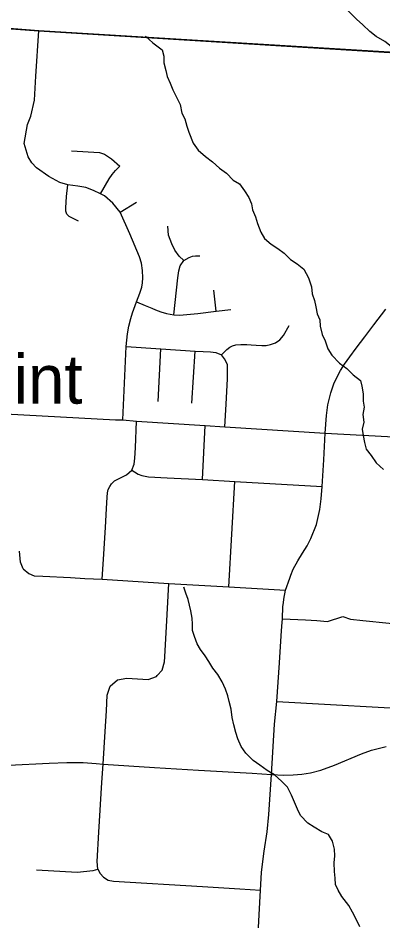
# Model space of a CAD drawing. Extents: x 0 to 34, y 0 to 22.
# Drawn here: x 4.859 to 5.448, y 5.875 to 7.332 of the extents above; entities that cross this region are included whole.
import ezdxf

# ---------------------------------------------------------------- set-up
doc = ezdxf.new("R2010")
doc.units = 0
for name, color, linetype in [('GM_X_City_Street', 7, 'Continuous'), ('GM_X_Corporation', 7, 'Continuous'), ('GM_X_County_Road', 7, 'Continuous'), ('GM_X_Minor_River', 7, 'Continuous'), ('GM_X_Township_Road', 7, 'Continuous'), ('GM_X_Unincorporated_Text', 7, 'Continuous')]:
    doc.layers.add(name, color=color, linetype=linetype)

msp = doc.modelspace()

# ---------------------------------------------------------------- linework, layer by layer
at = {"layer": 'GM_X_City_Street'}
for p, q in [((5.0238, 7.0188), (5.0499, 7.035)), ((5.1788, 6.8591), (5.1747, 6.893)), ((5.0849, 6.7133), (5.0895, 6.7981)), ((5.1392, 6.7103), (5.1448, 6.7947)), ((5.1928, 6.6725), (5.1949, 6.7087)), ((5.1566, 6.5872), (5.161, 6.6742)), ((5.1989, 6.4142), (5.2088, 6.584)), ((5.1989, 6.4142), (5.2908, 6.4087))]:
    msp.add_line(p, q, dxfattribs=at)
for points in [[(5.0282, 6.6834), (5.0336, 6.8021), (5.0356, 6.8225), (5.0377, 6.835), (5.0407, 6.847), (5.0438, 6.8564), (5.0502, 6.8742), (5.0553, 6.8879), (5.0585, 6.8979), (5.0596, 6.9048), (5.0601, 6.9129), (5.0599, 6.9249), (5.0583, 6.9364), (5.055, 6.9469), (5.0392, 6.984), (5.0238, 7.0188), (5.0118, 7.0332), (4.9983, 7.0451), (4.9922, 7.0487), (4.9809, 7.0541), (4.9682, 7.0585), (4.9552, 7.0608), (4.9391, 7.0631), (4.9261, 7.0668), (4.9087, 7.0765), (4.8888, 7.0904), (4.8811, 7.0987), (4.8753, 7.108), (4.8689, 7.1296), (4.8742, 7.1602), (4.8794, 7.1739), (4.8853, 7.1998), (4.8876, 7.2383), (4.8927, 7.3114)], [(4.9452, 7.1179), (4.9902, 7.1151), (4.9984, 7.1123), (5.01, 7.1052), (5.023, 7.0931)], [(4.9922, 7.0487), (5.0062, 7.0728), (5.0108, 7.0798), (5.016, 7.086), (5.023, 7.0931)], [(4.9565, 7.0041), (4.9412, 7.0117), (4.9376, 7.0158), (4.9363, 7.0204), (4.936, 7.0258), (4.9373, 7.0444), (4.9391, 7.0631)], [(5.1267, 6.9408), (5.119, 6.9481), (5.1119, 6.9574), (5.1071, 6.9678), (5.1017, 6.9818), (5.1004, 6.9961)], [(5.1106, 6.8534), (5.1167, 6.9129), (5.1185, 6.9243), (5.1208, 6.9321), (5.1267, 6.9408), (5.1352, 6.9456), (5.1402, 6.9476), (5.1451, 6.9486), (5.1522, 6.9486)], [(5.0502, 6.8742), (5.064, 6.8682), (5.0746, 6.8637), (5.081, 6.8614), (5.0892, 6.8581), (5.0984, 6.8555), (5.1106, 6.8534)], [(5.1106, 6.8534), (5.1195, 6.8525), (5.1492, 6.8555), (5.1788, 6.8591), (5.2025, 6.8619)], [(5.2763, 6.2287), (5.2811, 6.2913), (5.2836, 6.3349), (5.2846, 6.3507), (5.2856, 6.3624), (5.2865, 6.3823), (5.2873, 6.3881), (5.288, 6.3939), (5.2908, 6.4087), (5.2974, 6.428), (5.2994, 6.4329), (5.3031, 6.4424), (5.3104, 6.4561), (5.3179, 6.4682), (5.3255, 6.4802), (5.3316, 6.4921), (5.3403, 6.5144), (5.346, 6.5386), (5.3482, 6.5562), (5.3498, 6.5758), (5.3523, 6.6192), (5.3548, 6.6619), (5.3567, 6.6904), (5.3589, 6.7076), (5.3635, 6.727), (5.3687, 6.7415), (5.374, 6.753), (5.3794, 6.7633), (5.3858, 6.7734), (5.3941, 6.7854), (5.4044, 6.7992), (5.4185, 6.8178), (5.433, 6.8372), (5.4524, 6.8622)], [(5.1874, 6.7883), (5.1956, 6.797), (5.2007, 6.8008), (5.2051, 6.8029), (5.2106, 6.8045), (5.2184, 6.8054), (5.228, 6.805), (5.2354, 6.8045), (5.2434, 6.804), (5.2521, 6.8037), (5.2592, 6.8038), (5.2666, 6.8052), (5.2743, 6.808), (5.2815, 6.8129), (5.2875, 6.8197), (5.2967, 6.8358)], [(5.0336, 6.8021), (5.0895, 6.7981), (5.1448, 6.7947), (5.1576, 6.7941), (5.1696, 6.7935), (5.1782, 6.7922), (5.1874, 6.7883)], [(5.1949, 6.7087), (5.1972, 6.75), (5.1967, 6.7728), (5.1923, 6.782), (5.1874, 6.7883)], [(4.9947, 6.4261), (4.9967, 6.4588), (4.9998, 6.5099), (5.0017, 6.5403), (5.0026, 6.5588), (5.0032, 6.5657), (5.0045, 6.5709), (5.0068, 6.5759), (5.0095, 6.5801), (5.0144, 6.5851), (5.034, 6.5949), (5.0423, 6.6022), (5.0461, 6.6119), (5.0476, 6.6219), (5.0483, 6.6383), (5.0501, 6.6817)], [(5.0423, 6.6022), (5.0468, 6.5994), (5.0529, 6.5958), (5.0585, 6.594), (5.0695, 6.5918), (5.0998, 6.5901), (5.1566, 6.5872), (5.2088, 6.584), (5.3498, 6.5758)], [(4.8672, 6.4429), (4.8628, 6.4538), (4.8613, 6.4715)], [(4.8672, 6.4429), (4.8763, 6.4355), (4.8852, 6.432), (4.8989, 6.4314), (4.9434, 6.4288), (4.9666, 6.4272), (4.9947, 6.4261), (5.1025, 6.4195), (5.1989, 6.4142)], [(5.0834, 6.2707), (5.0916, 6.2794), (5.0952, 6.2929), (5.0956, 6.3012), (5.0995, 6.3691), (5.1025, 6.4195)], [(5.2856, 6.3624), (5.323, 6.3606), (5.341, 6.3599), (5.3585, 6.3578), (5.3832, 6.3659), (5.3956, 6.3618), (5.4153, 6.3599), (5.5001, 6.351), (5.5091, 6.3517), (5.532, 6.3601), (5.5458, 6.3663), (5.5558, 6.3687), (5.5719, 6.3698)], [(5.0078, 6.2537), (5.0194, 6.2638), (5.0346, 6.2663), (5.0689, 6.2646), (5.0821, 6.2692), (5.0834, 6.2707)], [(4.9944, 6.0979), (4.9963, 6.1279), (4.9993, 6.1804), (5.0015, 6.2137), (5.0029, 6.2391), (5.0078, 6.2537)], [(5.2681, 6.111), (5.2729, 6.1924), (5.2763, 6.2287)], [(5.2763, 6.2287), (5.5265, 6.2146), (5.542, 6.2134), (5.548, 6.2091), (5.5508, 6.2045), (5.5487, 6.155)], [(5.2681, 6.111), (5.2879, 6.11), (5.3031, 6.1103), (5.3167, 6.1115), (5.3309, 6.1136), (5.3473, 6.1179), (5.3697, 6.1263), (5.4131, 6.1445), (5.4293, 6.1503), (5.4423, 6.1537), (5.4532, 6.156)], [(4.6232, 6.1114), (4.6591, 6.1164), (4.6822, 6.1183), (4.7245, 6.12), (4.7771, 6.1227), (4.8142, 6.1247), (4.8442, 6.1259), (4.909, 6.1291), (4.9374, 6.1303), (4.9638, 6.1302), (4.9851, 6.1286), (4.9963, 6.1279), (5.079, 6.1223), (5.1503, 6.1181), (5.237, 6.1134), (5.2681, 6.111)], [(5.245, 5.8246), (5.2454, 5.8346), (5.2502, 5.9241), (5.252, 5.9527), (5.2543, 5.9747), (5.2562, 5.9871), (5.2611, 6.0184), (5.2638, 6.0465), (5.2681, 6.111)], [(4.9878, 5.9583), (4.9865, 5.9703), (4.9895, 6.0178), (4.9944, 6.0979)], [(4.8888, 5.9573), (4.9545, 5.9533), (4.98, 5.9562), (4.9878, 5.9583)], [(4.9878, 5.9583), (4.9912, 5.951), (4.9967, 5.9451), (5.0042, 5.9406), (5.0127, 5.9386), (5.1568, 5.9302), (5.2169, 5.9264), (5.2502, 5.9241)]]:
    msp.add_lwpolyline(points, dxfattribs=at)
at = {"layer": 'GM_X_Corporation'}
for points in [[(4.7965, 7.3194), (4.8925, 7.3119), (5.4671, 7.2768), (6.364, 7.2257), (6.4094, 7.2208), (6.5353, 7.2165), (6.5502, 7.2155), (6.602, 7.2128), (6.6092, 7.2124), (6.6231, 7.2116), (7.2238, 7.1747), (7.2909, 7.1701), (7.3502, 7.1668), (7.6217, 7.1516), (7.8118, 7.1421), (7.8248, 7.359)], [(8.2072, 7.1212), (7.8118, 7.1421), (7.6217, 7.1516), (7.3502, 7.1668), (7.2909, 7.1701), (7.2238, 7.1747), (6.6231, 7.2116), (6.6092, 7.2124), (6.602, 7.2128), (6.5502, 7.2155), (6.5353, 7.2165), (6.4094, 7.2208), (6.364, 7.2257), (5.4671, 7.2768), (4.8925, 7.3119), (4.7965, 7.3194)], [(4.7965, 7.3194), (4.8925, 7.3119), (5.4671, 7.2768), (6.364, 7.2257), (6.4094, 7.2208), (6.5353, 7.2165), (6.5502, 7.2155), (6.602, 7.2128), (6.6092, 7.2124), (6.6231, 7.2116), (7.2238, 7.1747), (7.2909, 7.1701), (7.3502, 7.1668), (7.6217, 7.1516), (7.8118, 7.1421), (8.2072, 7.1212)], [(7.7166, 5.5308), (7.7544, 6.1605), (7.7758, 6.5063), (7.7733, 6.5379), (7.7824, 6.6705), (7.7909, 6.7772), (7.8118, 7.1421), (7.6217, 7.1516), (7.3502, 7.1668), (7.2909, 7.1701), (7.2238, 7.1747), (6.6231, 7.2116), (6.6092, 7.2124), (6.602, 7.2128), (6.5502, 7.2155), (6.5353, 7.2165), (6.4094, 7.2208), (6.364, 7.2257), (5.4671, 7.2768), (4.8925, 7.3119), (4.7965, 7.3194)]]:
    msp.add_lwpolyline(points, dxfattribs=at)
at = {"layer": 'GM_X_County_Road'}
for p, q in [((4.7967, 7.3189), (4.8927, 7.3114)), ((4.8927, 7.3114), (5.3187, 7.2853)), ((5.3187, 7.2853), (5.4673, 7.2762))]:
    msp.add_line(p, q, dxfattribs=at)
msp.add_lwpolyline([(4.8077, 6.6952), (4.8387, 6.6933), (5.0164, 6.6837), (5.0282, 6.6834), (5.0501, 6.6817), (5.161, 6.6742), (5.1928, 6.6725), (5.3548, 6.6619), (5.4855, 6.6549), (5.5101, 6.6532), (5.693, 6.6431), (5.765, 6.6395), (5.848, 6.6352), (5.9037, 6.6319), (5.9594, 6.6291), (6.0161, 6.625), (6.0291, 6.6247), (6.0386, 6.6229), (6.0491, 6.6191), (6.0557, 6.616), (6.0657, 6.6099), (6.0907, 6.5915), (6.0994, 6.5866)], dxfattribs=at)
at = {"layer": 'GM_X_Minor_River'}
for points in [[(5.4777, 7.27), (5.4662, 7.2823), (5.4507, 7.2944), (5.4367, 7.3027), (5.4268, 7.3106), (5.4155, 7.3216), (5.4052, 7.3303), (5.378, 7.3576)], [(5.0767, 7.2924), (5.0647, 7.3032)], [(5.0767, 7.2924), (5.0915, 7.2808), (5.0941, 7.2705), (5.094, 7.2599), (5.0973, 7.2474), (5.0996, 7.2379), (5.1044, 7.2272), (5.1085, 7.2166), (5.1149, 7.2048), (5.1205, 7.1926), (5.123, 7.1789), (5.1279, 7.1694), (5.1312, 7.158), (5.1346, 7.1481), (5.1413, 7.1303), (5.1495, 7.1188), (5.1615, 7.1089), (5.1728, 7.1001), (5.1841, 7.0901), (5.1954, 7.0817), (5.2063, 7.0703), (5.2161, 7.0645), (5.2244, 7.0535), (5.2311, 7.0424), (5.2356, 7.0325), (5.2374, 7.0227), (5.2419, 7.0112), (5.2452, 7.0006), (5.2508, 6.9865), (5.2568, 6.9766), (5.2673, 6.9671), (5.2783, 6.9602), (5.2884, 6.9525), (5.2986, 6.9426), (5.3091, 6.9353), (5.3201, 6.9269), (5.3275, 6.9128), (5.3324, 6.8984), (5.3338, 6.887), (5.3372, 6.8763), (5.3394, 6.8661), (5.3416, 6.8547), (5.3457, 6.8448), (5.3467, 6.8349), (5.3497, 6.8213), (5.3545, 6.811), (5.359, 6.7985), (5.3654, 6.7882), (5.3778, 6.7752), (5.3894, 6.7664), (5.4, 6.7565), (5.4116, 6.7473), (5.4135, 6.7378), (5.4157, 6.7256), (5.416, 6.7139), (5.4174, 6.704), (5.4154, 6.6923), (5.4169, 6.6801), (5.4142, 6.6688), (5.416, 6.6585), (5.4178, 6.6471), (5.4208, 6.6365), (5.4287, 6.6258), (5.4369, 6.6144), (5.4486, 6.6033)], [(5.284, 6.1), (5.2727, 6.1103), (5.261, 6.1177), (5.249, 6.1261), (5.2381, 6.1334), (5.2264, 6.1457), (5.2189, 6.1564), (5.2134, 6.1686), (5.2104, 6.1789), (5.2071, 6.1914), (5.2046, 6.2029), (5.2028, 6.2165), (5.1995, 6.2287), (5.1977, 6.2382), (5.1936, 6.2489), (5.1884, 6.2607), (5.1813, 6.2726), (5.1735, 6.2829), (5.1667, 6.2932), (5.1611, 6.3027), (5.1533, 6.3127), (5.148, 6.3222), (5.1436, 6.3337), (5.1403, 6.3436), (5.1404, 6.3538), (5.1401, 6.3633), (5.1375, 6.3751), (5.1335, 6.3934), (5.1295, 6.404), (5.1265, 6.4136), (5.1269, 6.4128)], [(5.4104, 5.8653), (5.4052, 5.8763), (5.3985, 5.8889), (5.3925, 5.8996), (5.3816, 5.9138), (5.3753, 5.9241), (5.3712, 5.9336), (5.3705, 5.9435), (5.3695, 5.9545), (5.3692, 5.9686), (5.3701, 5.9799), (5.3698, 5.9906), (5.3665, 6.0031), (5.3598, 6.0142), (5.3492, 6.0185), (5.3368, 6.0258), (5.3266, 6.0324), (5.315, 6.045), (5.3098, 6.0549), (5.3001, 6.0778), (5.2938, 6.0904), (5.284, 6.1)]]:
    msp.add_lwpolyline(points, dxfattribs=at)
at = {"layer": 'GM_X_Township_Road'}
for p, q in [((4.7967, 7.3189), (4.8927, 7.3114)), ((4.8927, 7.3114), (5.3187, 7.2853)), ((5.3187, 7.2853), (5.4673, 7.2762))]:
    msp.add_line(p, q, dxfattribs=at)

# ---------------------------------------------------------------- texts
at = {"layer": 'GM_X_Unincorporated_Text'}
msp.add_text('Flint', height=0.07898, rotation=0, dxfattribs=at).set_placement((4.7636, 6.7097))

doc.saveas('drawing.dxf')
